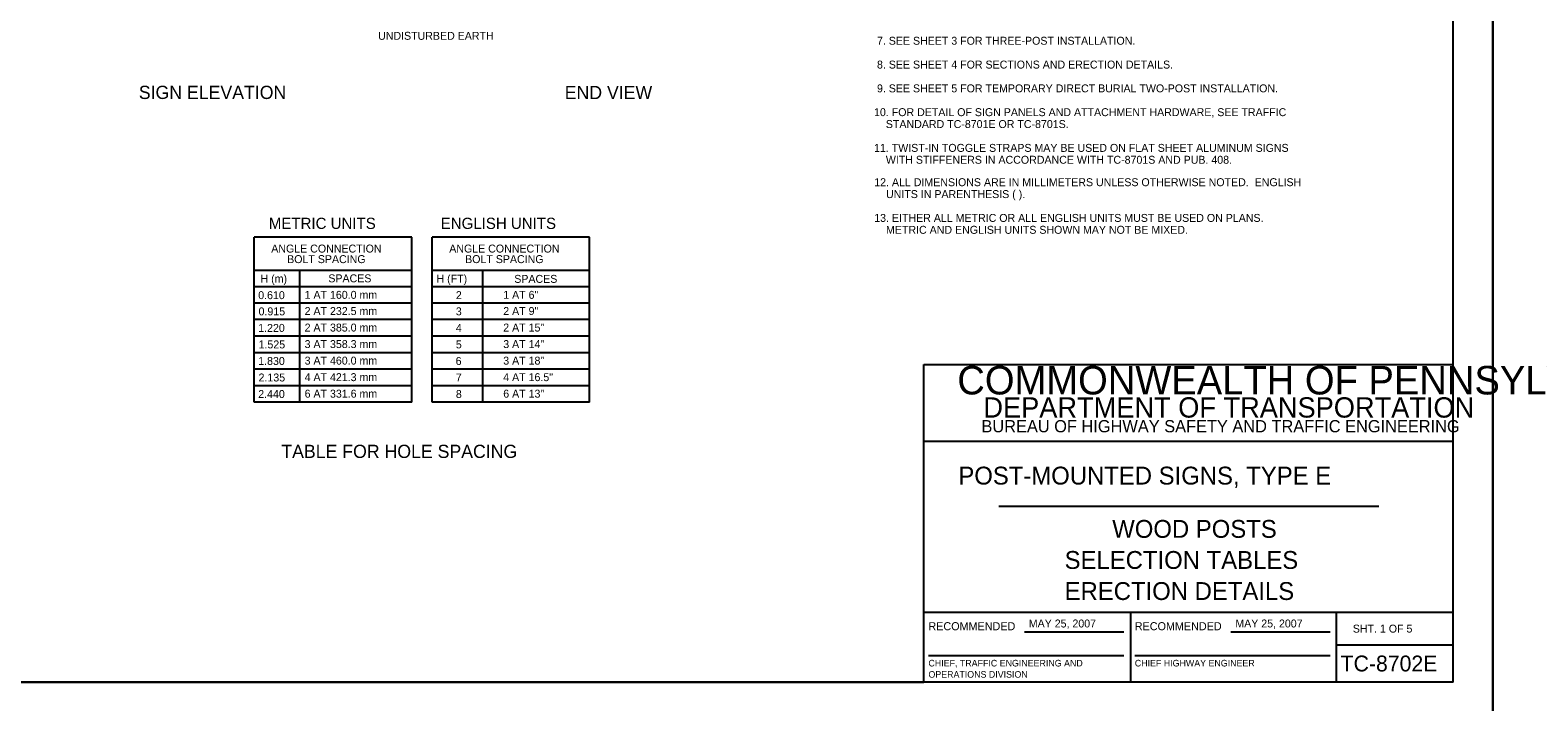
# Model space of a CAD drawing. Extents: x -1958 to 628, y -879 to 309.
# Drawn here: x -1670 to -1100, y -277 to -23 of the extents above; entities that cross this region are included whole.
import ezdxf

# ---------------------------------------------------------------- set-up
doc = ezdxf.new("R2010")
doc.units = 0
for name, color, linetype in [('1', 7, 'Continuous'), ('2', 7, 'Continuous'), ('3', 7, 'Continuous'), ('PLT-BNDY', 7, 'Continuous')]:
    doc.layers.add(name, color=color, linetype=linetype)

msp = doc.modelspace()

# ---------------------------------------------------------------- linework, layer by layer
at = {"layer": '1'}
for p, q in [((-1132.39, -269.56), (-1132.39, 294.44)), ((-1332.39, -269.56), (-1332.39, -149.56)), ((-1332.39, -149.56), (-1132.39, -149.56)), ((-1132.39, -178.56), (-1332.39, -178.56)), ((-1304.14, -203.06), (-1160.51, -203.06)), ((-1332.39, -243.19), (-1132.39, -243.19)), ((-1254.39, -243.19), (-1254.39, -269.56)), ((-1176.51, -269.56), (-1176.51, -243.19)), ((-1294.45, -250.62), (-1256.83, -250.62)), ((-1216.45, -250.62), (-1178.83, -250.62)), ((-1176.51, -255.56), (-1132.39, -255.56)), ((-1330.7, -259.51), (-1256.83, -259.51)), ((-1252.7, -259.51), (-1178.83, -259.51)), ((-1132.39, -269.56), (-1918.39, -269.56)), ((-1918.39, -269.56), (-1332.39, -269.56))]:
    msp.add_line(p, q, dxfattribs=at)
at = {"layer": '2'}
for p, q in [((-1526.02, -101.42), (-1585.52, -101.42)), ((-1585.52, -163.79), (-1585.52, -101.42)), ((-1526.02, -163.79), (-1526.02, -101.42)), ((-1458.75, -101.42), (-1518.25, -101.42)), ((-1518.25, -163.79), (-1518.25, -101.42)), ((-1458.75, -163.79), (-1458.75, -101.42)), ((-1526.02, -113.92), (-1585.52, -113.92)), ((-1568.27, -163.79), (-1568.27, -113.92)), ((-1458.75, -113.92), (-1518.25, -113.92)), ((-1499.15, -163.61), (-1499.15, -113.73)), ((-1526.02, -120.17), (-1585.52, -120.17)), ((-1458.75, -120.17), (-1518.25, -120.17)), ((-1526.02, -126.29), (-1585.52, -126.29)), ((-1458.75, -126.29), (-1518.25, -126.29)), ((-1526.02, -132.54), (-1585.52, -132.54)), ((-1458.75, -132.54), (-1518.25, -132.54)), ((-1526.02, -138.79), (-1585.52, -138.79)), ((-1458.75, -138.79), (-1518.25, -138.79)), ((-1526.02, -145.04), (-1585.52, -145.04)), ((-1458.75, -145.04), (-1518.25, -145.04)), ((-1526.02, -151.29), (-1585.52, -151.29)), ((-1458.75, -151.29), (-1518.25, -151.29)), ((-1526.02, -157.54), (-1585.52, -157.54)), ((-1458.75, -157.54), (-1518.25, -157.54)), ((-1526.02, -163.79), (-1585.52, -163.79)), ((-1458.75, -163.79), (-1518.25, -163.79))]:
    msp.add_line(p, q, dxfattribs=at)
at = {"layer": 'PLT-BNDY'}
for points in [[(-1958.39, 309.44), (-1117.39, 309.44), (-1117.39, -284.56), (-1958.39, -284.56)], [(-1117.39, 309.44), (-276.39, 309.44), (-276.39, -284.56), (-1117.39, -284.56)]]:
    msp.add_lwpolyline(points, close=True, dxfattribs=at)

# ---------------------------------------------------------------- texts
at = {"layer": '1'}
for s, height, p in [(' 7. SEE SHEET 3 FOR THREE-POST INSTALLATION.', 3, (-1351.26, -28.6)), (' 8. SEE SHEET 4 FOR SECTIONS AND ERECTION DETAILS.', 3, (-1351.26, -37.6)), (' 9. SEE SHEET 5 FOR TEMPORARY DIRECT BURIAL TWO-POST INSTALLATION.', 3, (-1351.26, -46.6)), ('10. FOR DETAIL OF SIGN PANELS AND ATTACHMENT HARDWARE, SEE TRAFFIC', 3, (-1351.26, -55.6)), ('    STANDARD TC-8701E OR TC-8701S.', 3, (-1351.26, -60.1)), ('11. TWIST-IN TOGGLE STRAPS MAY BE USED ON FLAT SHEET ALUMINUM SIGNS', 3, (-1351.26, -69.1)), ('    WITH STIFFENERS IN ACCORDANCE WITH TC-8701S AND PUB. 408. ', 3, (-1351.26, -73.6)), ('COMMONWEALTH OF PENNSYLVANIA', 10.7827, (-1319.79, -160.83)), ('DEPARTMENT OF TRANSPORTATION', 7.6838, (-1309.93, -169.58)), ('BUREAU OF HIGHWAY SAFETY AND TRAFFIC ENGINEERING', 4.6252, (-1310.66, -175.15)), ('POST-MOUNTED SIGNS, TYPE E', 6.7492, (-1319.39, -194.89)), ('WOOD POSTS', 6.75, (-1261.23, -215.04)), ('SELECTION TABLES', 6.75, (-1279.23, -226.79)), ('ERECTION DETAILS', 6.75, (-1279.23, -238.54)), ('RECOMMENDED', 3.048, (-1330.7, -249.99)), ('RECOMMENDED', 3.048, (-1252.7, -249.99)), ('SHT. 1 OF 5', 3, (-1170.3, -250.88)), ('CHIEF, TRAFFIC ENGINEERING AND', 2.5, (-1330.7, -263.68)), ('CHIEF HIGHWAY ENGINEER', 2.5, (-1252.7, -263.68)), ('TC-8702E', 6, (-1174.91, -265.56)), ('OPERATIONS DIVISION', 2.5, (-1330.7, -267.93))]:
    msp.add_text(s, height=height, dxfattribs=at).set_placement(p)
at = {"layer": '2'}
for s, height, p in [('12. ALL DIMENSIONS ARE IN MILLIMETERS UNLESS OTHERWISE NOTED.  ENGLISH', 3, (-1351.19, -82.08)), ('    UNITS IN PARENTHESIS ( ).', 3, (-1351.19, -86.58)), ('METRIC UNITS', 4.25, (-1580.01, -98.26)), ('ENGLISH UNITS', 4.25, (-1515.04, -98.26)), ('13. EITHER ALL METRIC OR ALL ENGLISH UNITS MUST BE USED ON PLANS.', 3, (-1351.19, -95.58)), ('    METRIC AND ENGLISH UNITS SHOWN MAY NOT BE MIXED.     ', 3, (-1351.19, -100.08)), ('MAY 25, 2007', 3, (-1292.78, -248.93)), ('MAY 25, 2007', 3, (-1214.71, -248.93))]:
    msp.add_text(s, height=height, dxfattribs=at).set_placement(p)
at = {"layer": '3'}
for s, height, p in [('UNDISTURBED EARTH', 3, (-1538.71, -26.73)), ('SIGN ELEVATION', 5, (-1629.15, -49.12)), ('END VIEW', 5, (-1468.17, -49.17)), ('ANGLE CONNECTION', 3, (-1579.09, -107.17)), ('BOLT SPACING', 3, (-1573.09, -111.17)), ('ANGLE CONNECTION', 3, (-1511.82, -107.17)), ('BOLT SPACING', 3, (-1505.82, -111.17)), ('H (m)', 3, (-1583.14, -118.54)), ('SPACES', 3, (-1557.52, -118.43)), ('H (FT)', 3, (-1516.63, -118.54)), ('SPACES', 3, (-1487.24, -118.63)), ('0.610', 3, (-1584.02, -124.79)), ('1 AT 160.0 mm', 3, (-1566.48, -124.67)), ('2', 3, (-1509.32, -124.79)), ('1 AT 6"', 3, (-1491.41, -124.67)), ('0.915', 3, (-1583.89, -130.92)), ('2 AT 232.5 mm', 3, (-1566.48, -130.79)), ('3', 3, (-1509.33, -130.92)), ('2 AT 9"', 3, (-1491.41, -130.79)), ('1.220', 3, (-1584.02, -137.17)), ('2 AT 385.0 mm', 3, (-1566.48, -137.04)), ('4', 3, (-1509.32, -137.17)), ('2 AT 15"', 3, (-1491.41, -137.04)), ('1.525', 3, (-1583.89, -143.42)), ('3 AT 358.3 mm', 3, (-1566.48, -143.29)), ('5', 3, (-1509.33, -143.42)), ('3 AT 14"', 3, (-1491.41, -143.29)), ('1.830', 3, (-1584.02, -149.67)), ('3 AT 460.0 mm', 3, (-1566.48, -149.54)), ('6', 3, (-1509.4, -149.67)), ('3 AT 18"', 3, (-1491.41, -149.54)), ('2.135', 3, (-1583.89, -155.92)), ('4 AT 421.3 mm', 3, (-1566.48, -155.79)), ('7', 3, (-1509.33, -155.92)), ('4 AT 16.5"', 3, (-1491.41, -155.79)), ('2.440', 3, (-1584.02, -162.17)), ('6 AT 331.6 mm', 3, (-1566.48, -162.04)), ('8', 3, (-1509.32, -162.17)), ('6 AT 13"', 3, (-1491.41, -162.04)), ('TABLE FOR HOLE SPACING', 5, (-1575.29, -184.85))]:
    msp.add_text(s, height=height, dxfattribs=at).set_placement(p)

doc.saveas('drawing.dxf')
